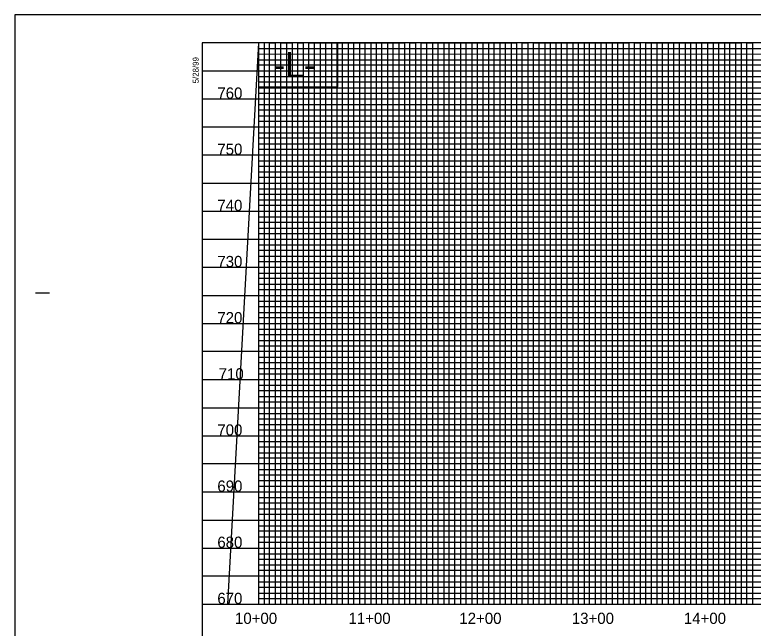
# Model space of a CAD drawing. Extents: x 1524869 to 1526553, y 501099 to 502199.
# Drawn here: x 1524869 to 1525527, y 501652 to 502199 of the extents above; entities that cross this region are included whole.
import ezdxf

# ---------------------------------------------------------------- set-up
doc = ezdxf.new("R2010")
doc.units = 0
for name, color, linetype in [('Exist Vertical Profile Horizontal Axis Label Major', 7, 'Continuous'), ('Exist Vertical Profile Vertical Axis Label', 7, 'Continuous'), ('Prop Grid Mask', 7, 'Continuous'), ('Prop Horizontal Alignment Curve and Spiral Data', 7, 'Continuous'), ('Sheet Layout Profile Border Port 1', 7, 'Continuous'), ('Sheet Plot Border Outside CELL', 7, 'Continuous'), ('Sheet Profile CELL', 7, 'Continuous'), ('Sheet Profile Grid Major CELL', 7, 'Continuous'), ('Sheet Profile Grid Middle CELL', 7, 'Continuous'), ('Sheet Profile Grid Minor CELL', 7, 'Continuous')]:
    doc.layers.add(name, color=color, linetype=linetype)

msp = doc.modelspace()

# ---------------------------------------------------------------- linework, layer by layer
at = {"layer": 'Prop Grid Mask'}
msp.add_lwpolyline([(1525086.08, 502134.52), (1525156.81, 502134.52), (1525156.81, 502173.56), (1525086.08, 502173.56)], close=True, dxfattribs=at)
at = {"layer": 'Sheet Layout Profile Border Port 1'}
msp.add_lwpolyline([(1525086.08, 502173.56), (1525058.64, 501673.56), (1526486.08, 501673.56), (1526486.08, 502012.51), (1526336.03, 502012.51), (1526336.08, 502173.56)], close=True, dxfattribs=at)
msp.add_lwpolyline([(1525086.08, 502173.56), (1525058.64, 501673.56), (1526486.08, 501673.56), (1526486.08, 502012.51), (1526336.03, 502012.51), (1526336.08, 502173.56)], close=True, dxfattribs=at)
at = {"layer": 'Sheet Plot Border Outside CELL'}
msp.add_lwpolyline([(1524869.08, 501098.56), (1526553.08, 501098.56), (1526553.08, 502198.56), (1524869.08, 502198.56)], close=True, dxfattribs=at)
at = {"layer": 'Sheet Profile CELL'}
for p, q in [((1524887.58, 501951.06), (1524900.08, 501951.06)), ((1525036.08, 501673.56), (1526536.08, 501673.56))]:
    msp.add_line(p, q, dxfattribs=at)
msp.add_lwpolyline([(1526536.08, 502173.56), (1525036.08, 502173.56), (1525036.08, 501123.56), (1526536.08, 501123.56)], close=True, dxfattribs=at)
at = {"layer": 'Sheet Profile Grid Major CELL'}
for points in [[(1525086.08, 502173.56), (1525086.08, 501673.56), (1525136.08, 501673.56), (1525136.08, 502173.56), (1525186.08, 502173.56), (1525186.08, 501673.56), (1525236.08, 501673.56), (1525236.08, 502173.56), (1525286.08, 502173.56), (1525286.08, 501673.56), (1525336.08, 501673.56), (1525336.08, 502173.56), (1525386.08, 502173.56), (1525386.08, 501673.56), (1525436.08, 501673.56), (1525436.08, 502173.56), (1525486.08, 502173.56), (1525486.08, 501673.56), (1525536.08, 501673.56)], [(1525036.08, 502123.56), (1526336.08, 502123.56)], [(1526336.08, 502073.56), (1525036.08, 502073.56), (1525036.08, 502023.56), (1526336.08, 502023.56)], [(1526536.08, 501973.56), (1525036.08, 501973.56), (1525036.08, 501923.56), (1526536.08, 501923.56)], [(1526536.08, 501873.56), (1525036.08, 501873.56), (1525036.08, 501823.56), (1526536.08, 501823.56)], [(1526536.08, 501773.56), (1525036.08, 501773.56), (1525036.08, 501773.56), (1525036.08, 501723.56), (1526536.08, 501723.56)]]:
    msp.add_lwpolyline(points, dxfattribs=at)
at = {"layer": 'Sheet Profile Grid Middle CELL'}
msp.add_line((1525036.08, 502148.56), (1526336.03, 502148.56), dxfattribs=at)
for points in [[(1525111.08, 502173.56), (1525111.08, 501673.56), (1525161.08, 501673.56), (1525161.08, 502173.56), (1525211.08, 502173.56), (1525211.08, 501673.56), (1525261.08, 501673.56), (1525261.08, 502173.56), (1525311.08, 502173.56), (1525311.08, 501673.56), (1525361.08, 501673.56), (1525361.08, 502173.56), (1525411.08, 502173.56), (1525411.08, 501673.56), (1525461.08, 501673.56), (1525461.08, 502173.56), (1525511.08, 502173.56), (1525511.08, 501673.56), (1525561.08, 501673.56)], [(1526336.08, 502098.56), (1525036.08, 502098.56), (1525036.08, 502048.56), (1526336.08, 502048.56)], [(1526536.08, 501998.56), (1525036.08, 501998.56), (1525036.08, 501948.56), (1526361.08, 501948.56)], [(1526536.08, 501898.56), (1525036.08, 501898.56), (1525036.08, 501848.56), (1526536.08, 501848.56)], [(1526536.08, 501798.56), (1525036.08, 501798.56), (1525036.08, 501748.56), (1526536.08, 501748.56)], [(1526536.08, 501698.56), (1525036.08, 501698.56)]]:
    msp.add_lwpolyline(points, dxfattribs=at)
at = {"layer": 'Sheet Profile Grid Minor CELL'}
for p, q in [((1525086.08, 502168.56), (1526187.87, 502168.56)), ((1525086.08, 502163.56), (1525086.08, 502163.56)), ((1526187.87, 502163.52), (1525086.08, 502163.21)), ((1525086.08, 502158.56), (1526336.08, 502158.56)), ((1526336.03, 502038.56), (1525086.08, 502038.56)), ((1526336.08, 502033.56), (1525086.08, 502033.56)), ((1526336.08, 502028.56), (1525086.08, 502028.56)), ((1525086.08, 502018.56), (1526336.08, 502018.56)), ((1526336.08, 502013.56), (1525086.08, 502013.56)), ((1525086.08, 502008.56), (1526486.08, 502008.56)), ((1526486.08, 501988.56), (1525086.08, 501988.56)), ((1525086.08, 501983.56), (1526486.08, 501983.56)), ((1526486.08, 501963.56), (1525086.08, 501963.56)), ((1525086.08, 501958.56), (1526486.08, 501958.56)), ((1526486.08, 501938.56), (1525086.08, 501938.56)), ((1525086.08, 501933.56), (1526486.08, 501933.56)), ((1526486.08, 501928.56), (1525086.08, 501928.56)), ((1525086.08, 501918.56), (1526486.08, 501918.56)), ((1526486.08, 501913.56), (1525086.08, 501913.56)), ((1525086.08, 501908.56), (1526486.08, 501908.56)), ((1526486.08, 501903.56), (1525086.08, 501903.56)), ((1525086.08, 501893.56), (1526486.08, 501893.56)), ((1526486.08, 501888.56), (1525086.08, 501888.56)), ((1525086.08, 501883.56), (1526486.08, 501883.56)), ((1526486.08, 501878.56), (1525086.08, 501878.56)), ((1525086.08, 501868.56), (1526486.08, 501868.56)), ((1526486.08, 501863.56), (1525086.08, 501863.56)), ((1525086.08, 501858.56), (1526486.08, 501858.56)), ((1526486.08, 501853.56), (1525086.08, 501853.56)), ((1525086.08, 501843.56), (1526486.08, 501843.56)), ((1526486.08, 501838.56), (1525086.08, 501838.56)), ((1525086.08, 501833.56), (1526486.08, 501833.56)), ((1526486.08, 501828.56), (1525086.08, 501828.56)), ((1525086.08, 501818.56), (1526486.08, 501818.56)), ((1526486.08, 501813.56), (1525086.08, 501813.56)), ((1525086.08, 501808.56), (1526486.08, 501808.56)), ((1526486.08, 501803.56), (1525086.08, 501803.56)), ((1525086.08, 501793.56), (1526486.08, 501793.56)), ((1526486.08, 501788.56), (1525086.08, 501788.56)), ((1526486.08, 501783.56), (1525086.08, 501783.56)), ((1526486.08, 501778.56), (1525086.08, 501778.56)), ((1525086.08, 501768.56), (1526486.08, 501768.56)), ((1526486.08, 501763.56), (1525086.08, 501763.56)), ((1525086.08, 501758.56), (1526486.08, 501758.56)), ((1526486.08, 501753.56), (1525086.08, 501753.56)), ((1525086.08, 501743.56), (1526486.08, 501743.56)), ((1526486.08, 501738.56), (1525086.08, 501738.56)), ((1525086.08, 501733.56), (1526486.08, 501733.56)), ((1526486.08, 501728.56), (1525086.08, 501728.56)), ((1525086.08, 501718.56), (1526486.08, 501718.56)), ((1526486.08, 501713.56), (1525086.08, 501713.56)), ((1525086.08, 501708.56), (1526486.08, 501708.56)), ((1526486.08, 501703.56), (1525086.08, 501703.56)), ((1525086.08, 501693.56), (1526486.08, 501693.56)), ((1526486.08, 501688.56), (1525086.08, 501688.56)), ((1525086.08, 501683.56), (1526486.08, 501683.56))]:
    msp.add_line(p, q, dxfattribs=at)
for points in [[(1525091.08, 502173.56), (1525091.08, 501673.56), (1525096.08, 501673.56), (1525096.08, 502173.56), (1525101.08, 502173.56), (1525101.08, 501673.56), (1525106.08, 501673.56), (1525106.08, 502173.56), (1525116.08, 502173.56), (1525116.08, 501673.56), (1525121.08, 501673.56), (1525121.08, 502173.56), (1525126.08, 502173.56), (1525126.08, 501673.56), (1525131.08, 501673.56), (1525141.08, 501673.56), (1525146.08, 501673.56), (1525146.08, 502173.56), (1525151.08, 502173.56), (1525151.08, 501673.56), (1525156.08, 501673.56), (1525156.08, 502173.56), (1525166.08, 502173.56), (1525166.08, 501673.56), (1525171.08, 501673.56), (1525171.08, 502173.56), (1525176.08, 502173.56), (1525176.08, 501673.56), (1525181.08, 501673.56), (1525181.08, 502173.56), (1525191.08, 502173.56), (1525191.08, 501673.56), (1525196.08, 501673.56), (1525196.08, 502173.56), (1525201.08, 502173.56), (1525201.08, 501673.56), (1525206.08, 501673.56), (1525206.08, 502173.56), (1525216.08, 502173.56), (1525216.08, 501673.56), (1525221.08, 501673.56), (1525221.08, 502173.56), (1525226.08, 502173.56), (1525226.08, 501673.56), (1525231.08, 501673.56), (1525231.08, 502173.56), (1525241.08, 502173.56), (1525241.08, 501673.56), (1525246.08, 501673.56), (1525246.08, 502173.56), (1525251.08, 502173.56), (1525251.08, 501673.56), (1525256.08, 501673.56), (1525256.08, 502173.56), (1525266.08, 502173.56), (1525266.08, 501673.56), (1525271.08, 501673.56), (1525271.08, 502173.56), (1525276.08, 502173.56), (1525276.08, 501673.56), (1525281.08, 501673.56), (1525281.08, 502173.56), (1525291.08, 502173.56), (1525291.08, 501673.56), (1525296.08, 501673.56), (1525296.08, 502173.56), (1525301.08, 502173.56), (1525301.08, 501673.56)], [(1525131.08, 501673.56), (1525131.08, 502173.56), (1525141.08, 502173.56), (1525141.08, 501673.56)], [(1525301.08, 501673.56), (1525306.08, 501673.56), (1525306.08, 502173.56), (1525316.08, 502173.56), (1525316.08, 501673.56), (1525321.08, 501673.56), (1525321.08, 502173.56), (1525326.08, 502173.56), (1525326.08, 501673.56), (1525331.08, 501673.56), (1525331.08, 502173.56), (1525341.08, 502173.56), (1525341.08, 501673.56), (1525346.08, 501673.56), (1525346.08, 502173.56), (1525351.08, 502173.56), (1525351.08, 501673.56), (1525356.08, 501673.56), (1525356.08, 502173.56), (1525366.08, 502173.56), (1525366.08, 501673.56), (1525371.08, 501673.56), (1525371.08, 502173.56), (1525376.08, 502173.56), (1525376.08, 501673.56), (1525381.08, 501673.56), (1525381.08, 502173.56), (1525391.08, 502173.56), (1525391.08, 501673.56), (1525396.08, 501673.56), (1525396.08, 502173.56), (1525401.08, 502173.56), (1525401.08, 501673.56), (1525406.08, 501673.56), (1525406.08, 502173.56), (1525416.08, 502173.56), (1525416.08, 501673.56), (1525421.08, 501673.56), (1525421.08, 502173.56), (1525426.08, 502173.56), (1525426.08, 501673.56), (1525431.08, 501673.56), (1525431.08, 502173.56), (1525441.08, 502173.56), (1525441.08, 501673.56), (1525446.08, 501673.56), (1525446.08, 502173.56), (1525451.08, 502173.56), (1525451.08, 501673.56), (1525456.08, 501673.56), (1525456.08, 502173.56), (1525466.08, 502173.56), (1525466.08, 501673.56), (1525471.08, 501673.56), (1525471.08, 502173.56), (1525476.08, 502173.56), (1525476.08, 501673.56), (1525481.08, 501673.56), (1525481.08, 502173.56), (1525491.08, 502173.56), (1525491.08, 501673.56), (1525496.08, 501673.56), (1525496.08, 502173.56), (1525501.08, 502173.56), (1525501.08, 501673.56), (1525506.08, 501673.56), (1525506.08, 502173.56), (1525516.08, 502173.56), (1525516.08, 501673.56), (1525521.08, 501673.56), (1525521.08, 502173.56), (1525526.08, 502173.56), (1525526.08, 501673.56), (1525531.08, 501673.56)], [(1526336.08, 502153.56), (1525086.08, 502153.56), (1525086.08, 502143.56), (1526336.08, 502143.56)], [(1526336.03, 502138.56), (1525086.08, 502138.56), (1525086.08, 502133.56), (1526336.08, 502133.56)], [(1526336.08, 502128.56), (1525086.08, 502128.56), (1525086.08, 502118.56), (1526336.08, 502118.56)], [(1526336.08, 502113.56), (1525086.08, 502113.56), (1525086.08, 502108.56), (1526336.08, 502108.56)], [(1526336.08, 502103.56), (1525086.08, 502103.56), (1525086.08, 502093.56), (1526336.08, 502093.56)], [(1526336.08, 502088.56), (1525086.08, 502088.56), (1525086.08, 502083.56), (1526336.08, 502083.56)], [(1526336.08, 502078.56), (1525086.08, 502078.56), (1525086.08, 502068.56), (1526336.08, 502068.56)], [(1526336.08, 502063.46), (1525086.18, 502063.46), (1525086.18, 502058.56), (1526336.08, 502058.56)], [(1526336.08, 502053.56), (1525086.08, 502053.56), (1525086.08, 502043.56), (1526336.08, 502043.56)], [(1526486.08, 502003.56), (1525086.08, 502003.56), (1525086.08, 501993.56), (1526486.08, 501993.56)], [(1526486.08, 501978.56), (1525086.08, 501978.56), (1525086.08, 501968.56), (1526486.08, 501968.56)], [(1526486.08, 501953.56), (1525086.08, 501953.56), (1525086.08, 501943.56), (1526486.08, 501943.56)], [(1526486.08, 501678.56), (1525086.08, 501678.56)]]:
    msp.add_lwpolyline(points, dxfattribs=at)

# ---------------------------------------------------------------- texts
at = {"layer": 'Exist Vertical Profile Horizontal Axis Label Major'}
for s, p in [('10+00', (1525065.21, 501656.06)), ('11+00', (1525166.27, 501656.06)), ('12+00', (1525265.05, 501656.06)), ('13+00', (1525365.21, 501656.06)), ('14+00', (1525465, 501656.06))]:
    msp.add_text(s, height=10, dxfattribs=at).set_placement(p)
at = {"layer": 'Exist Vertical Profile Vertical Axis Label'}
for s, p in [('760', (1525049.51, 502123.81)), ('750', (1525049.51, 502073.81)), ('740', (1525049.51, 502023.81)), ('730', (1525049.51, 501973.81)), ('720', (1525049.51, 501923.81)), ('710', (1525050.71, 501873.81)), ('700', (1525049.51, 501823.81)), ('690', (1525049.51, 501773.81)), ('680', (1525049.51, 501723.81)), ('670', (1525049.51, 501673.81))]:
    msp.add_text(s, height=10, dxfattribs=at).set_placement(p)
at = {"layer": 'Prop Horizontal Alignment Curve and Spiral Data'}
msp.add_text('-L-', height=22.5, rotation=360, dxfattribs=at).set_placement((1525099.8, 502142.79))
at = {"layer": 'Sheet Profile CELL'}
msp.add_text('5/28/99', height=5.25, rotation=90, dxfattribs=at).set_placement((1525032.84, 502137.47))

doc.saveas('drawing.dxf')
